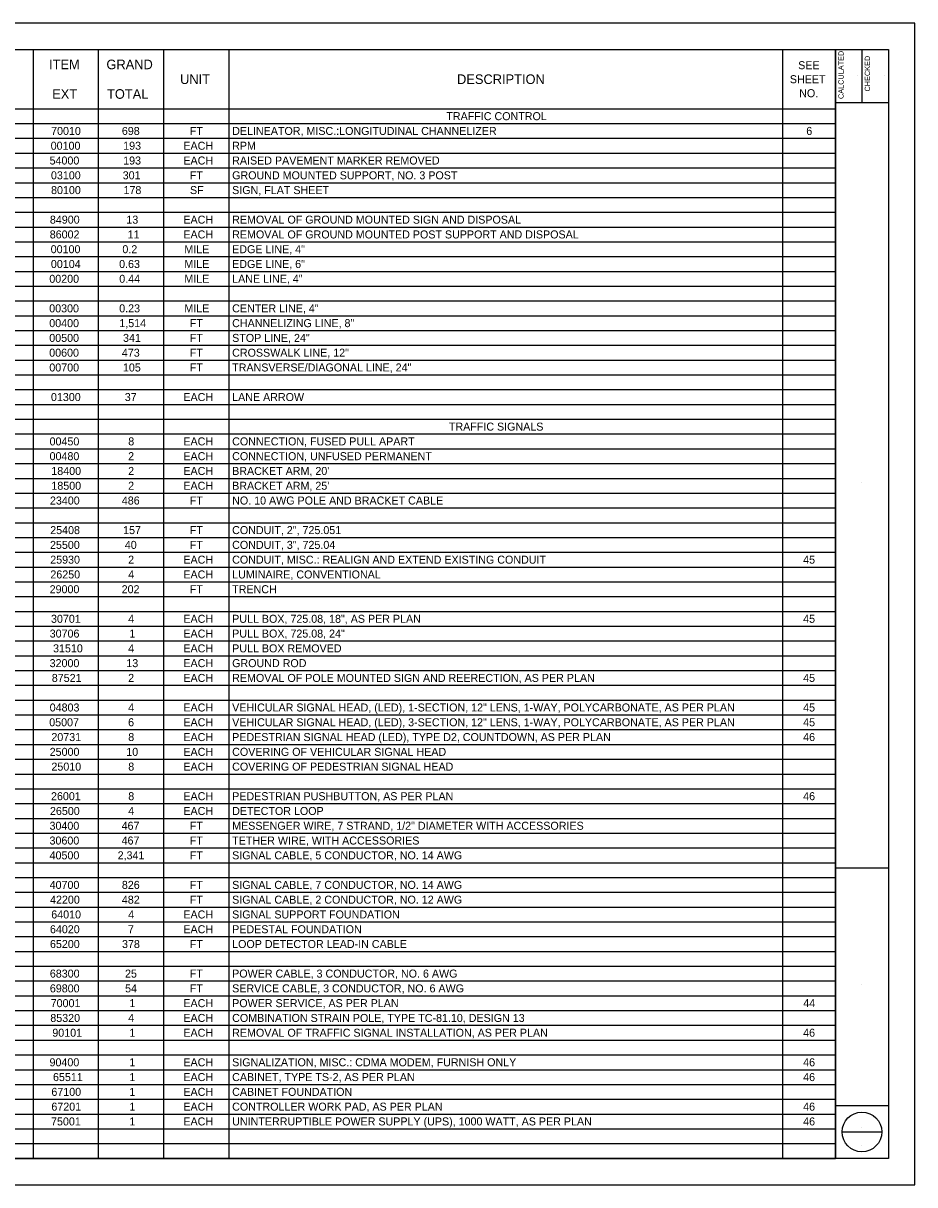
# Model space of a CAD drawing. Extents: x 0 to 34, y 0 to 22.
# Drawn here: x 17.11 to 34, y 0 to 22 of the extents above; entities that cross this region are included whole.
import ezdxf

# ---------------------------------------------------------------- set-up
doc = ezdxf.new("R2010")
doc.units = 0
for name, color, linetype in [('Default', 7, 'Continuous'), ('SH_Border', 7, 'Continuous'), ('SH_Cut_Line', 7, 'Continuous'), ('SH_Data', 7, 'Continuous')]:
    doc.layers.add(name, color=color, linetype=linetype)

msp = doc.modelspace()

# ---------------------------------------------------------------- linework, layer by layer
at = {"layer": 'Default'}
for p, q in [((2, 21.5), (32.5, 21.5)), ((17.299, 21.5), (17.299, 0.5)), ((18.535, 21.5), (18.535, 0.5)), ((19.77, 21.5), (19.77, 0.5)), ((21.005, 21.5), (21.005, 0.5)), ((31.495, 21.5), (31.495, 0.5)), ((32.5, 21.5), (32.5, 0.5)), ((2, 20.38), (32.5, 20.38)), ((2, 20.1), (32.5, 20.1)), ((2, 19.82), (32.5, 19.82)), ((2, 19.54), (32.5, 19.54)), ((2, 19.26), (32.5, 19.26)), ((2, 18.98), (32.5, 18.98)), ((2, 18.7), (32.5, 18.7)), ((2, 18.42), (32.5, 18.42)), ((2, 18.14), (32.5, 18.14)), ((2, 17.86), (32.5, 17.86)), ((2, 17.58), (32.5, 17.58)), ((2, 17.3), (32.5, 17.3)), ((2, 17.02), (32.5, 17.02)), ((2, 16.74), (32.5, 16.74)), ((2, 16.46), (32.5, 16.46)), ((2, 16.18), (32.5, 16.18)), ((2, 15.9), (32.5, 15.9)), ((2, 15.62), (32.5, 15.62)), ((2, 15.34), (32.5, 15.34)), ((2, 15.06), (32.5, 15.06)), ((2, 14.78), (32.5, 14.78)), ((2, 14.5), (32.5, 14.5)), ((2, 14.22), (32.5, 14.22)), ((2, 13.94), (32.5, 13.94)), ((2, 13.66), (32.5, 13.66)), ((2, 13.38), (32.5, 13.38)), ((2, 13.1), (32.5, 13.1)), ((2, 12.82), (32.5, 12.82)), ((2, 12.54), (32.5, 12.54)), ((2, 12.26), (32.5, 12.26)), ((2, 11.98), (32.5, 11.98)), ((2, 11.7), (32.5, 11.7)), ((2, 11.42), (32.5, 11.42)), ((2, 11.14), (32.5, 11.14)), ((2, 10.86), (32.5, 10.86)), ((2, 10.58), (32.5, 10.58)), ((2, 10.3), (32.5, 10.3)), ((2, 10.02), (32.5, 10.02)), ((2, 9.74), (32.5, 9.74)), ((2, 9.46), (32.5, 9.46)), ((2, 9.18), (32.5, 9.18)), ((2, 8.9), (32.5, 8.9)), ((2, 8.62), (32.5, 8.62)), ((2, 8.34), (32.5, 8.34)), ((2, 8.06), (32.5, 8.06)), ((2, 7.78), (32.5, 7.78)), ((2, 7.5), (32.5, 7.5)), ((2, 7.22), (32.5, 7.22)), ((2, 6.94), (32.5, 6.94)), ((2, 6.66), (32.5, 6.66)), ((2, 6.38), (32.5, 6.38)), ((2, 6.1), (32.5, 6.1)), ((2, 5.82), (32.5, 5.82)), ((2, 5.54), (32.5, 5.54)), ((2, 5.26), (32.5, 5.26)), ((2, 4.98), (32.5, 4.98)), ((2, 4.7), (32.5, 4.7)), ((2, 4.42), (32.5, 4.42)), ((2, 4.14), (32.5, 4.14)), ((2, 3.86), (32.5, 3.86)), ((2, 3.58), (32.5, 3.58)), ((2, 3.3), (32.5, 3.3)), ((2, 3.02), (32.5, 3.02)), ((2, 2.74), (32.5, 2.74)), ((2, 2.46), (32.5, 2.46)), ((2, 2.18), (32.5, 2.18)), ((2, 1.9), (32.5, 1.9)), ((2, 1.62), (32.5, 1.62)), ((2, 1.34), (32.5, 1.34)), ((2, 1.06), (32.5, 1.06)), ((2, 0.78), (32.5, 0.78)), ((2, 0.5), (32.5, 0.5))]:
    msp.add_line(p, q, dxfattribs=at)
at = {"layer": 'SH_Border'}
for p, q in [((32.5, 0.5), (32.5, 21.5)), ((33, 21.5), (33, 20.5)), ((32.5, 20.5), (33.5, 20.5)), ((32.5, 6), (33.5, 6)), ((32.5, 1.5), (33.5, 1.5))]:
    msp.add_line(p, q, dxfattribs=at)
msp.add_lwpolyline([(2, 21.5), (33.5, 21.5), (33.5, 0.5), (2, 0.5)], close=True, dxfattribs=at)
at = {"layer": 'SH_Cut_Line'}
msp.add_lwpolyline([(0, 0), (34, 0), (34, 22), (0, 22)], close=True, dxfattribs=at)
at = {"layer": 'SH_Data'}
for p, q in [((32.92, 21.004), (32.92, 21.004)), ((33.42, 21.004), (33.42, 21.004)), ((33, 13.292), (33, 13.292)), ((33, 3.792), (33, 3.792)), ((32.625, 1), (33.375, 1)), ((33, 1.085), (33, 1.085)), ((33, 0.745), (33, 0.745))]:
    msp.add_line(p, q, dxfattribs=at)
msp.add_circle((33, 1), 0.375, dxfattribs=at)

# ---------------------------------------------------------------- texts
at = {"layer": 'Default'}
for s, height, p in [('ITEM', 0.1818, (17.603, 21.129)), ('GRAND', 0.1818, (18.69, 21.129)), ('SEE', 0.1515, (31.792, 21.129)), ('UNIT', 0.1818, (20.085, 20.849)), ('DESCRIPTION', 0.18184, (25.331, 20.849)), ('SHEET', 0.1515, (31.634, 20.864)), ('EXT', 0.1818, (17.662, 20.569)), ('TOTAL', 0.1818, (18.701, 20.569)), ('NO.', 0.1515, (31.811, 20.599)), ('TRAFFIC CONTROL', 0.15153, (25.128, 20.164)), ('70010', 0.1515, (17.642, 19.884)), ('698', 0.1515, (18.982, 19.884)), ('FT', 0.1515, (20.268, 19.884)), ('DELINEATOR, MISC.:LONGITUDINAL CHANNELIZER', 0.15153, (21.071, 19.884)), ('6', 0.152, (31.945, 19.884)), ('00100', 0.1515, (17.634, 19.604)), ('193', 0.1515, (19.007, 19.604)), ('EACH', 0.1515, (20.147, 19.604)), ('RPM ', 0.1515, (21.071, 19.604)), ('54000', 0.1515, (17.613, 19.324)), ('193', 0.1515, (19.007, 19.324)), ('EACH', 0.1515, (20.147, 19.324)), ('RAISED PAVEMENT MARKER REMOVED ', 0.15153, (21.071, 19.324)), ('03100', 0.1515, (17.639, 19.044)), ('301', 0.1515, (18.998, 19.044)), ('FT', 0.1515, (20.268, 19.044)), ('GROUND MOUNTED SUPPORT, NO. 3 POST ', 0.15153, (21.071, 19.044)), ('80100', 0.1515, (17.641, 18.764)), ('178', 0.1515, (19.013, 18.764)), ('SF', 0.1515, (20.272, 18.764)), ('SIGN, FLAT SHEET ', 0.15153, (21.071, 18.764)), ('84900', 0.1515, (17.619, 18.204)), ('13', 0.1515, (19.067, 18.204)), ('EACH', 0.1515, (20.147, 18.204)), ('REMOVAL OF GROUND MOUNTED SIGN AND DISPOSAL ', 0.15153, (21.071, 18.204)), ('86002', 0.1515, (17.616, 17.924)), ('11', 0.1515, (19.092, 17.924)), ('EACH', 0.1515, (20.147, 17.924)), ('REMOVAL OF GROUND MOUNTED POST SUPPORT AND DISPOSAL ', 0.15153, (21.071, 17.924)), ('00100', 0.1515, (17.634, 17.644)), ('0.2', 0.1515, (18.992, 17.644)), ('MILE', 0.1515, (20.166, 17.644)), ('EDGE LINE, 4" ', 0.15153, (21.071, 17.644)), ('00104', 0.1515, (17.638, 17.364)), ('0.63', 0.1515, (18.93, 17.364)), ('MILE', 0.1515, (20.166, 17.364)), ('EDGE LINE, 6" ', 0.15153, (21.071, 17.364)), ('00200', 0.1515, (17.608, 17.084)), ('0.44', 0.1515, (18.933, 17.084)), ('MILE', 0.1515, (20.166, 17.084)), ('LANE LINE, 4" ', 0.15153, (21.071, 17.084)), ('00300', 0.1515, (17.606, 16.524)), ('0.23', 0.1515, (18.932, 16.524)), ('MILE', 0.1515, (20.166, 16.524)), ('CENTER LINE, 4"', 0.15153, (21.071, 16.524)), ('00400', 0.1515, (17.607, 16.244)), ('1,514', 0.1515, (18.934, 16.244)), ('FT', 0.1515, (20.268, 16.244)), ('CHANNELIZING LINE, 8" ', 0.15153, (21.071, 16.244)), ('00500', 0.1515, (17.607, 15.964)), ('341', 0.1515, (19.004, 15.964)), ('FT', 0.1515, (20.268, 15.964)), ('STOP LINE, 24"', 0.15153, (21.071, 15.964)), ('00600', 0.1515, (17.606, 15.684)), ('473', 0.1515, (18.982, 15.684)), ('FT', 0.1515, (20.268, 15.684)), ('CROSSWALK LINE, 12"', 0.15153, (21.071, 15.684)), ('00700', 0.1515, (17.608, 15.404)), ('105', 0.1515, (19.002, 15.404)), ('FT', 0.1515, (20.268, 15.404)), ('TRANSVERSE/DIAGONAL LINE, 24"', 0.15153, (21.071, 15.404)), ('01300', 0.1515, (17.639, 14.844)), ('37', 0.1515, (19.037, 14.844)), ('EACH', 0.1515, (20.147, 14.844)), ('LANE ARROW ', 0.15153, (21.071, 14.844)), ('TRAFFIC SIGNALS', 0.15153, (25.176, 14.284)), ('00450', 0.1515, (17.613, 14.004)), ('8', 0.152, (19.103, 14.004)), ('EACH', 0.1515, (20.147, 14.004)), ('CONNECTION, FUSED PULL APART ', 0.15153, (21.071, 14.004)), ('00480', 0.1515, (17.613, 13.724)), ('2', 0.152, (19.101, 13.724)), ('EACH', 0.1515, (20.147, 13.724)), ('CONNECTION, UNFUSED PERMANENT ', 0.15153, (21.071, 13.724)), ('18400', 0.1515, (17.646, 13.444)), ('2', 0.152, (19.101, 13.444)), ('EACH', 0.1515, (20.147, 13.444)), ("BRACKET ARM, 20' ", 0.15153, (21.071, 13.444)), ('18500', 0.1515, (17.647, 13.164)), ('2', 0.152, (19.101, 13.164)), ('EACH', 0.1515, (20.147, 13.164)), ("BRACKET ARM, 25' ", 0.15153, (21.071, 13.164)), ('23400', 0.1515, (17.62, 12.884)), ('486', 0.1515, (18.981, 12.884)), ('FT', 0.1515, (20.268, 12.884)), ('NO. 10 AWG POLE AND BRACKET CABLE ', 0.15153, (21.071, 12.884)), ('25408', 0.1515, (17.625, 12.324)), ('157', 0.1515, (19.006, 12.324)), ('FT', 0.1515, (20.268, 12.324)), ('CONDUIT, 2", 725.051 ', 0.15153, (21.071, 12.324)), ('25500', 0.1515, (17.621, 12.044)), ('40', 0.1515, (19.038, 12.044)), ('FT', 0.1515, (20.268, 12.044)), ('CONDUIT, 3", 725.04 ', 0.15153, (21.071, 12.044)), ('25930', 0.1515, (17.625, 11.764)), ('2', 0.152, (19.101, 11.764)), ('EACH', 0.1515, (20.147, 11.764)), ('CONDUIT, MISC.: REALIGN AND EXTEND EXISTING CONDUIT', 0.15153, (21.071, 11.764)), ('45', 0.1515, (31.886, 11.764)), ('26250', 0.1515, (17.628, 11.484)), ('4', 0.152, (19.102, 11.484)), ('EACH', 0.1515, (20.147, 11.484)), ('LUMINAIRE, CONVENTIONAL ', 0.15153, (21.071, 11.484)), ('29000', 0.1515, (17.614, 11.204)), ('202', 0.1515, (18.978, 11.204)), ('FT', 0.1515, (20.268, 11.204)), ('TRENCH ', 0.1515, (21.071, 11.204)), ('30701', 0.1515, (17.64, 10.644)), ('4', 0.152, (19.102, 10.644)), ('EACH', 0.1515, (20.147, 10.644)), ('PULL BOX, 725.08, 18", AS PER PLAN ', 0.15153, (21.071, 10.644)), ('45', 0.1515, (31.886, 10.644)), ('30706', 0.1515, (17.615, 10.364)), ('1', 0.152, (19.124, 10.364)), ('EACH', 0.1515, (20.147, 10.364)), ('PULL BOX, 725.08, 24" ', 0.15153, (21.071, 10.364)), ('31510', 0.1515, (17.679, 10.084)), ('4', 0.152, (19.102, 10.084)), ('EACH', 0.1515, (20.147, 10.084)), ('PULL BOX REMOVED ', 0.15153, (21.071, 10.084)), ('32000', 0.1515, (17.614, 9.804)), ('13', 0.1515, (19.067, 9.804)), ('EACH', 0.1515, (20.147, 9.804)), ('GROUND ROD ', 0.15153, (21.071, 9.804)), ('87521', 0.1515, (17.655, 9.524)), ('2', 0.152, (19.101, 9.524)), ('EACH', 0.1515, (20.147, 9.524)), ('REMOVAL OF POLE MOUNTED SIGN AND REERECTION, AS PER PLAN ', 0.15153, (21.071, 9.524)), ('45', 0.1515, (31.886, 9.524)), ('04803', 0.1515, (17.615, 8.964)), ('4', 0.152, (19.102, 8.964)), ('EACH', 0.1515, (20.147, 8.964)), ('VEHICULAR SIGNAL HEAD, (LED), 1-SECTION, 12" LENS, 1-WAY, POLYCARBONATE, AS PER PLAN ', 0.15153, (21.071, 8.964)), ('45', 0.1515, (31.886, 8.964)), ('05007', 0.1515, (17.606, 8.684)), ('6', 0.152, (19.1, 8.684)), ('EACH', 0.1515, (20.147, 8.684)), ('VEHICULAR SIGNAL HEAD, (LED), 3-SECTION, 12" LENS, 1-WAY, POLYCARBONATE, AS PER PLAN ', 0.15153, (21.071, 8.684)), ('45', 0.1515, (31.886, 8.684)), ('20731', 0.1515, (17.647, 8.404)), ('8', 0.152, (19.103, 8.404)), ('EACH', 0.1515, (20.147, 8.404)), ('PEDESTRIAN SIGNAL HEAD (LED), TYPE D2, COUNTDOWN, AS PER PLAN ', 0.15153, (21.071, 8.404)), ('46', 0.1515, (31.886, 8.404)), ('25000', 0.1515, (17.615, 8.124)), ('10', 0.1515, (19.066, 8.124)), ('EACH', 0.1515, (20.147, 8.124)), ('COVERING OF VEHICULAR SIGNAL HEAD ', 0.15153, (21.071, 8.124)), ('25010', 0.1515, (17.648, 7.844)), ('8', 0.152, (19.103, 7.844)), ('EACH', 0.1515, (20.147, 7.844)), ('COVERING OF PEDESTRIAN SIGNAL HEAD ', 0.15153, (21.071, 7.844)), ('26001', 0.1515, (17.64, 7.284)), ('8', 0.152, (19.103, 7.284)), ('EACH', 0.1515, (20.147, 7.284)), ('PEDESTRIAN PUSHBUTTON, AS PER PLAN ', 0.15153, (21.071, 7.284)), ('46', 0.1515, (31.886, 7.284)), ('26500', 0.1515, (17.62, 7.004)), ('4', 0.152, (19.102, 7.004)), ('EACH', 0.1515, (20.147, 7.004)), ('DETECTOR LOOP ', 0.15153, (21.071, 7.004)), ('30400', 0.1515, (17.612, 6.724)), ('467', 0.1515, (18.977, 6.724)), ('FT', 0.1515, (20.268, 6.724)), ('MESSENGER WIRE, 7 STRAND, 1/2" DIAMETER WITH ACCESSORIES ', 0.15153, (21.071, 6.724)), ('30600', 0.1515, (17.612, 6.444)), ('467', 0.1515, (18.977, 6.444)), ('FT', 0.1515, (20.268, 6.444)), ('TETHER WIRE, WITH ACCESSORIES ', 0.15153, (21.071, 6.444)), ('40500', 0.1515, (17.613, 6.164)), ('2,341', 0.1515, (18.902, 6.164)), ('FT', 0.1515, (20.268, 6.164)), ('SIGNAL CABLE, 5 CONDUCTOR, NO. 14 AWG ', 0.15153, (21.071, 6.164)), ('40700', 0.1515, (17.614, 5.604)), ('826', 0.1515, (18.982, 5.604)), ('FT', 0.1515, (20.268, 5.604)), ('SIGNAL CABLE, 7 CONDUCTOR, NO. 14 AWG ', 0.15153, (21.071, 5.604)), ('42200', 0.1515, (17.622, 5.324)), ('482', 0.1515, (18.982, 5.324)), ('FT', 0.1515, (20.268, 5.324)), ('SIGNAL CABLE, 2 CONDUCTOR, NO. 12 AWG ', 0.15153, (21.071, 5.324)), ('64010', 0.1515, (17.645, 5.044)), ('4', 0.152, (19.102, 5.044)), ('EACH', 0.1515, (20.147, 5.044)), ('SIGNAL SUPPORT FOUNDATION ', 0.15153, (21.071, 5.044)), ('64020', 0.1515, (17.62, 4.764)), ('7', 0.152, (19.097, 4.764)), ('EACH', 0.1515, (20.147, 4.764)), ('PEDESTAL FOUNDATION ', 0.15153, (21.071, 4.764)), ('65200', 0.1515, (17.62, 4.484)), ('378', 0.1515, (18.985, 4.484)), ('FT', 0.1515, (20.268, 4.484)), ('LOOP DETECTOR LEAD-IN CABLE ', 0.15153, (21.071, 4.484)), ('68300', 0.1515, (17.618, 3.924)), ('25', 0.1515, (19.042, 3.924)), ('FT', 0.1515, (20.268, 3.924)), ('POWER CABLE, 3 CONDUCTOR, NO. 6 AWG ', 0.15153, (21.071, 3.924)), ('69800', 0.1515, (17.618, 3.644)), ('54', 0.1515, (19.043, 3.644)), ('FT', 0.1515, (20.268, 3.644)), ('SERVICE CABLE, 3 CONDUCTOR, NO. 6 AWG ', 0.15153, (21.071, 3.644)), ('70001', 0.1515, (17.634, 3.364)), ('1', 0.152, (19.124, 3.364)), ('EACH', 0.1515, (20.147, 3.364)), ('POWER SERVICE, AS PER PLAN ', 0.15153, (21.071, 3.364)), ('44', 0.1515, (31.888, 3.364)), ('85320', 0.1515, (17.627, 3.084)), ('4', 0.152, (19.102, 3.084)), ('EACH', 0.1515, (20.147, 3.084)), ('COMBINATION STRAIN POLE, TYPE TC-81.10, DESIGN 13 ', 0.15153, (21.071, 3.084)), ('90101', 0.1515, (17.665, 2.804)), ('1', 0.152, (19.124, 2.804)), ('EACH', 0.1515, (20.147, 2.804)), ('REMOVAL OF TRAFFIC SIGNAL INSTALLATION, AS PER PLAN ', 0.15153, (21.071, 2.804)), ('46', 0.1515, (31.886, 2.804)), ('90400', 0.1515, (17.612, 2.244)), ('1', 0.152, (19.124, 2.244)), ('EACH', 0.1515, (20.147, 2.244)), ('SIGNALIZATION, MISC.: CDMA MODEM, FURNISH ONLY', 0.15153, (21.071, 2.244)), ('46', 0.1515, (31.886, 2.244)), ('65511', 0.1515, (17.678, 1.964)), ('1', 0.152, (19.124, 1.964)), ('EACH', 0.1515, (20.147, 1.964)), ('CABINET, TYPE TS-2, AS PER PLAN ', 0.15153, (21.071, 1.964)), ('46', 0.1515, (31.886, 1.964)), ('67100', 0.1515, (17.647, 1.684)), ('1', 0.152, (19.124, 1.684)), ('EACH', 0.1515, (20.147, 1.684)), ('CABINET FOUNDATION ', 0.15153, (21.071, 1.684)), ('67201', 0.1515, (17.647, 1.404)), ('1', 0.152, (19.124, 1.404)), ('EACH', 0.1515, (20.147, 1.404)), ('CONTROLLER WORK PAD, AS PER PLAN ', 0.15153, (21.071, 1.404)), ('46', 0.1515, (31.886, 1.404)), ('75001', 0.1515, (17.641, 1.124)), ('1', 0.152, (19.124, 1.124)), ('EACH', 0.1515, (20.147, 1.124)), ('UNINTERRUPTIBLE POWER SUPPLY (UPS), 1000 WATT, AS PER PLAN ', 0.15153, (21.071, 1.124)), ('46', 0.1515, (31.886, 1.124))]:
    msp.add_text(s, height=height, dxfattribs=at).set_placement(p)
at = {"layer": 'SH_Data'}
for s, p in [('CALCULATED', (32.652, 20.565)), ('CHECKED', (33.152, 20.708))]:
    msp.add_text(s, height=0.1, rotation=90, dxfattribs=at).set_placement(p)

doc.saveas('drawing.dxf')
